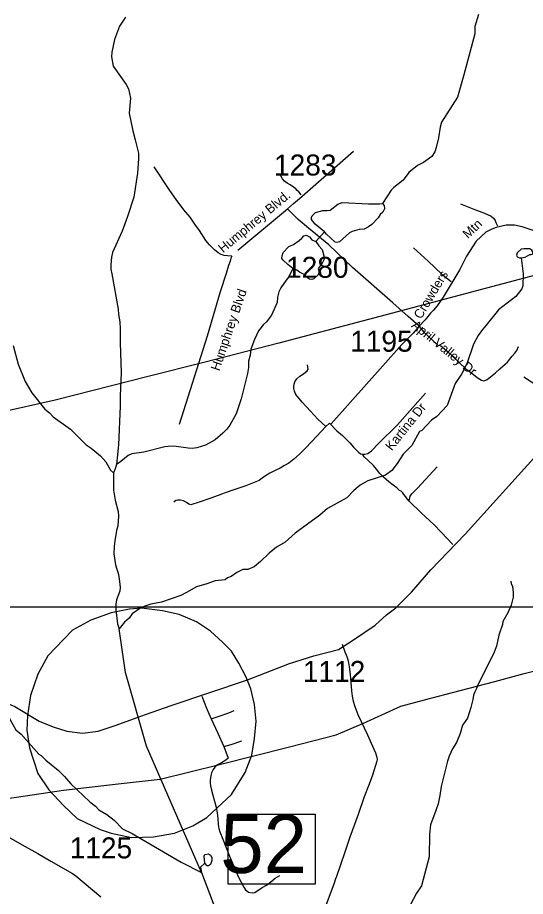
# Model space of a CAD drawing. Extents: x 1268485 to 1426702, y 514839 to 616766.
# Drawn here: x 1319574 to 1323145, y 527765 to 533949 of the extents above; entities that cross this region are included whole.
import ezdxf

# ---------------------------------------------------------------- set-up
doc = ezdxf.new("R2010")
doc.units = 0
for name, color, linetype in [('Old_Level_10', 7, 'Continuous'), ('Old_Level_11', 7, 'Continuous'), ('Old_Level_3', 7, 'Continuous'), ('Old_Level_31', 7, 'Continuous'), ('Old_Level_32', 7, 'Continuous'), ('Old_Level_35', 7, 'Continuous'), ('Old_Level_50', 7, 'Continuous'), ('Old_Level_56', 7, 'Continuous'), ('Old_Level_59', 7, 'Continuous'), ('Old_Level_62', 7, 'Continuous'), ('Old_Level_63', 7, 'Continuous'), ('Old_Level_8', 7, 'Continuous')]:
    doc.layers.add(name, color=color, linetype=linetype)

msp = doc.modelspace()

# ---------------------------------------------------------------- linework, layer by layer
at = {"layer": 'Old_Level_3'}
msp.add_lwpolyline([(1320374.254, 528179.02), (1320529.254, 528185.479), (1320677.796, 528211.312), (1320806.963, 528262.979), (1320903.838, 528321.103), (1321078.213, 528482.562), (1321175.088, 528637.562), (1321220.296, 528760.27), (1321239.671, 528876.521), (1321252.588, 528999.229), (1321239.671, 529115.479), (1321213.838, 529225.271), (1321181.546, 529309.229), (1321129.88, 529406.104), (1321078.213, 529490.062), (1321013.629, 529554.645), (1320929.671, 529632.146), (1320832.796, 529696.729), (1320710.088, 529748.396), (1320593.837, 529774.229), (1320445.296, 529793.604), (1320361.338, 529787.145), (1320232.171, 529761.312), (1320090.088, 529709.646), (1319960.921, 529638.604), (1319896.338, 529574.02), (1319786.546, 529457.77), (1319715.504, 529328.604), (1319663.838, 529180.062), (1319644.463, 529037.979), (1319638.004, 528934.646), (1319657.379, 528811.937), (1319715.504, 528631.104), (1319793.004, 528514.854), (1319896.338, 528405.062), (1319993.213, 528314.645), (1320154.671, 528237.145), (1320232.171, 528211.312), (1320374.254, 528179.02)], dxfattribs=at)
at = {"layer": 'Old_Level_31'}
msp.add_line((1320424.412, 529026.51), (1320424.412, 529026.51), dxfattribs=at)
msp.add_lwpolyline([(1321054.079, 528343.583), (1321665.834, 528343.583), (1321665.834, 527851.725), (1321054.079, 527851.725), (1321054.079, 528343.583)], dxfattribs=at)
at = {"layer": 'Old_Level_32'}
msp.add_line((1321122.398, 532313.014), (1321471.76, 532603.131), dxfattribs=at)
for points in [[(1321471.76, 532603.131), (1321513.515, 532640.421), (1321556.826, 532675.62), (1321936.012, 533008.804)], [(1322397.94, 531778.778), (1322321.212, 531846.106), (1322213.13, 531941.677), (1321928.472, 532191.922), (1321763.389, 532350.705), (1321620.563, 532466.815), (1321547.67, 532527.679), (1321507.453, 532567.416), (1321471.76, 532603.131)], [(1323957.426, 532145.829), (1323546.481, 532304.305), (1323430.573, 532355.426), (1323346.276, 532390.188), (1323270.41, 532428.019), (1323184.006, 532456.646), (1323122.891, 532477.095), (1323068.098, 532489.364), (1323009.09, 532489.364), (1322939.545, 532473.005), (1322907.935, 532460.737), (1322865.786, 532440.288), (1322798.349, 532376.898), (1322730.911, 532270.566), (1322682.686, 532177.311), (1322565.361, 531981.792), (1322523.219, 531920.864), (1322499.107, 531891.281), (1322477.75, 531868.86), (1322439.348, 531823.596), (1322397.94, 531778.778)], [(1322397.94, 531778.778), (1322356.401, 531729.282), (1322275.71, 531647.907), (1321778.36, 531091.708)], [(1320422.195, 529026.86), (1320473.092, 529045.164), (1320653.021, 529108.515), (1321189.477, 529288.566), (1321486.026, 529405.266), (1321655.96, 529458.614), (1321831.317, 529503.547), (1321936.928, 529571.055), (1322087.268, 529673.681), (1322167.162, 529745.909), (1322234.211, 529796.385), (1322342.868, 529905.853), (1322480.695, 530062.757), (1322720.696, 530315.252), (1323225.707, 530872.787), (1323239.898, 530886.275)], [(1318113.271, 529418.979), (1318158.493, 529431.424), (1318177.54, 529434.146), (1318193.865, 529439.591), (1318283.655, 529450.482), (1318340.795, 529458.65), (1318487.724, 529450.482), (1318850.398, 529355.252), (1319336.873, 529191.872), (1319553.454, 529101.847), (1319726.719, 528998.484), (1319823.348, 528958.473), (1319919.976, 528928.464), (1320029.933, 528915.127), (1320139.89, 528928.464), (1320259.843, 528968.475), (1320422.195, 529026.86)], [(1318113.271, 529418.979), (1318114.959, 529292.566), (1318123.121, 529082.92), (1318131.284, 528971.289), (1318150.33, 528884.163), (1318166.656, 528846.045), (1318215.633, 528756.196), (1318259.167, 528704.466), (1318338.073, 528647.289), (1318422.422, 528606.448), (1318650.476, 528511.012), (1318777.093, 528471.001), (1318970.351, 528387.644), (1319130.287, 528327.627), (1319193.596, 528304.286), (1319480.149, 528200.923), (1319606.767, 528127.57), (1319716.723, 528067.552), (1319806.687, 528014.204), (1319959.961, 527927.513), (1319983.285, 527910.841), (1320159.863, 527763.521)]]:
    msp.add_lwpolyline(points, dxfattribs=at)
at = {"layer": 'Old_Level_35'}
for p, q in [((1323489.705, 531183.886), (1323134.247, 531418.619)), ((1321768.293, 531096.072), (1321740.201, 531071.568))]:
    msp.add_line(p, q, dxfattribs=at)
for points in [[(1321080.035, 532269.739), (1321048.97, 532273.122), (1321026.517, 532276.454), (1321005.499, 532282.298), (1320984.584, 532293.986), (1320957.824, 532315.773), (1320924.503, 532349.197), (1320898.462, 532381.748), (1320853.35, 532451.21), (1320820.747, 532496.321), (1320788.144, 532544.816), (1320743.853, 532597.463), (1320687.873, 532668.514), (1320645.223, 532732.9), (1320533.982, 532900.12)], [(1321567.342, 532701.117), (1321551.45, 532722.852), (1321540.582, 532733.772), (1321529.715, 532743.768), (1321513.003, 532756.328), (1321490.345, 532771.399), (1321470.352, 532784.727), (1321450.257, 532798.927), (1321436.826, 532813.998), (1321416.834, 532847.422)], [(1322688.772, 532639.704), (1322781.045, 532600.949), (1322856.402, 532572.447), (1322904.281, 532551.941), (1322920.891, 532539.126), (1322932.784, 532522.261), (1322937.295, 532508.573), (1322947.547, 532483.506)], [(1322356.895, 532328.435), (1322460.651, 532234.931), (1322557.538, 532144.811), (1322623.77, 532092.369)], [(1321080.035, 532269.739), (1321074.089, 532257.179), (1321068.245, 532234.623), (1321057.377, 532205.353), (1321040.665, 532148.553), (1320998.015, 532019.831), (1320906.869, 531707.127), (1320710.327, 531086.024)], [(1322397.905, 531787.815), (1322403.749, 531766.9), (1322432.149, 531734.296), (1322498.586, 531672.883), (1322516.22, 531655.3), (1322529.651, 531645.253), (1322544.62, 531641.049), (1322558.871, 531633.565), (1322596.498, 531599.269), (1322679.954, 531523.195), (1322725.989, 531477.263), (1322767.922, 531447.121), (1322793.758, 531427.077), (1322813.033, 531412.877), (1322834.769, 531396.935), (1322847.277, 531393.602), (1322859.785, 531396.115), (1322874.856, 531403.65), (1322899.155, 531421.182), (1322933.399, 531448.813), (1322965.079, 531478.084), (1322984.354, 531493.924), (1323002.706, 531510.687), (1323017.778, 531525.707), (1323032.849, 531543.239), (1323052.124, 531567.486), (1323069.656, 531588.453), (1323083.907, 531607.626), (1323096.415, 531636.076)], [(1321740.201, 531071.568), (1321686.169, 531124.061), (1321632.753, 531179.99), (1321575.031, 531243.863), (1321531.253, 531297.228), (1321520.795, 531320.809), (1321517.207, 531338.29), (1321516.386, 531353.207), (1321518.129, 531368.945), (1321523.358, 531387.297), (1321536.481, 531408.315), (1321558.422, 531425.795), (1321576.774, 531437.176), (1321596.049, 531452.914), (1321610.915, 531463.422), (1321616.144, 531473.06), (1321614.401, 531489.618), (1321612.658, 531505.356)], [(1321998.361, 530877.384), (1322014.97, 530876.513), (1322035.988, 530882.612), (1322062.235, 530901.016), (1322113.703, 530955.253), (1322242.373, 531081.205), (1322353.511, 531205.364), (1322441.786, 531305.994)], [(1321768.293, 531096.072), (1321818.12, 531042.707), (1321858.413, 531007.694), (1321883.737, 530982.319), (1321909.984, 530956.124), (1321936.23, 530927.263), (1321958.171, 530903.63), (1321972.115, 530890.507), (1321985.238, 530880.87), (1321998.361, 530877.384)], [(1321740.201, 531071.568), (1321642.391, 530967.504), (1321596.049, 530916.754), (1321556.577, 530877.384), (1321517.207, 530843.242), (1321480.502, 530814.382), (1321451.59, 530796.952), (1321420.114, 530779.42), (1321384.333, 530761.939), (1321347.628, 530742.664), (1321317.896, 530724.312), (1321294.212, 530707.703), (1321271.452, 530692.837), (1321236.49, 530677.92), (1321178.768, 530654.339), (1321102.591, 530629.015), (1321026.619, 530601.896), (1321003.038, 530593.131), (1320932.09, 530566.884), (1320851.607, 530539.765), (1320791.22, 530521.362), (1320779.019, 530526.642), (1320761.487, 530536.229), (1320740.469, 530548.48), (1320719.451, 530552.889), (1320701.202, 530554.632), (1320686.335, 530551.146), (1320673.212, 530539.765)], [(1322326.855, 530547.814), (1322313.424, 530563.449), (1322303.786, 530576.367), (1322290.868, 530594.053), (1322282.768, 530604.921), (1322270.465, 530615.891), (1322260.213, 530621.325), (1322239.708, 530640.293), (1322215.204, 530658.696), (1322185.471, 530683.199), (1322147.024, 530715.547), (1322120.777, 530741.793), (1322098.017, 530771.577), (1322076.076, 530797.823), (1322038.654, 530833.605), (1322011.485, 530858.981), (1321998.361, 530877.384)], [(1322326.855, 530547.814), (1322330.956, 530570.267), (1322334.339, 530581.801), (1322346.027, 530597.488), (1322385.397, 530636.96), (1322524.832, 530787.315)], [(1322634.125, 530240.851), (1322552.72, 530329.434), (1322503.712, 530379.825), (1322411.951, 530464.101), (1322326.855, 530547.814)], [(1321855.132, 529539.881), (1321873.792, 529487.643), (1321888.761, 529454.015), (1321897.476, 529422.949), (1321906.088, 529380.606), (1321912.342, 529325.857), (1321916.135, 529271.057), (1321922.389, 529212.617), (1321927.413, 529175.246), (1321933.462, 529139.209), (1321944.74, 529101.838), (1321967.091, 529045.808), (1322034.348, 528901.502), (1322079.152, 528800.668), (1322091.66, 528775.805), (1322096.581, 528752.121), (1322101.502, 528731.001), (1322100.272, 528717.314)], [(1320870.575, 529175.246), (1320903.383, 529091.175), (1320934.859, 529015.306)], [(1320934.859, 529015.306), (1320992.171, 529034.017), (1321058.608, 529057.29), (1321096.03, 529072.515)], [(1320934.859, 529015.306), (1320980.38, 528918.368), (1321023.646, 528821.481)], [(1321023.646, 528821.481), (1321075.012, 528835.475), (1321150.881, 528861.209)], [(1321023.646, 528821.481), (1321055.122, 528738.64), (1321037.59, 528724.644), (1321007.242, 528704.754), (1320980.38, 528690.76), (1320960.593, 528673.791), (1320948.905, 528657.439), (1320938.345, 528635.293), (1320932.501, 528616.634), (1320929.63, 528599.665), (1320927.887, 528580.442), (1320928.502, 528562.858), (1320930.245, 528543.635), (1320936.602, 528512.108), (1320947.162, 528478.839), (1320958.235, 528435.06), (1320969.41, 528392.46), (1320976.894, 528352.167), (1320981.61, 528314.182), (1320985.096, 528270.454), (1320989.71, 528242.414), (1320996.784, 528219.191), (1321018.007, 528168.8), (1321064.964, 528049.767), (1321127.71, 527900.899), (1321163.902, 527830.566), (1321176.205, 527812.573), (1321196.71, 527795.143), (1321222.957, 527790.735), (1321242.232, 527793.247), (1321293.905, 527828.106), (1321323.125, 527845.484), (1321353.575, 527868.552), (1321385.973, 527894.081), (1321417.141, 527913.356)], [(1322100.272, 528717.314), (1322070.54, 528618.992), (1322045.523, 528555.476)], [(1322045.523, 528555.476), (1322011.997, 528465.869), (1321969.654, 528342.684), (1321909.881, 528182.179), (1321873.792, 528076.372), (1321815.352, 527905.871), (1321809.406, 527889.006)], [(1321809.406, 527889.006), (1321799.153, 527859.837), (1321741.841, 527700.563)]]:
    msp.add_lwpolyline(points, dxfattribs=at)
at = {"layer": 'Old_Level_50'}
msp.add_line((1320424.412, 529029.179), (1320424.412, 529029.179), dxfattribs=at)
at = {"layer": 'Old_Level_56'}
for points in [[(1323366.294, 532177.376), (1322870.978, 532044.675), (1322166.251, 531856.96), (1321411.081, 531658.454), (1320883.684, 531522.597), (1320491.102, 531423.847), (1319838.818, 531256.887), (1319440.632, 531168.053), (1318922.163, 531078.039), (1318268.965, 530955.12), (1317830.82, 530869.291), (1317691.971, 530840.471), (1317442.112, 530764.26), (1316936.195, 530611.963), (1316289.347, 530416.88), (1315543.694, 530194.172)], [(1316620.183, 528035.863), (1316843.479, 528084.795), (1317196.816, 528132.51), (1317632.76, 528208.376), (1318074.503, 528274.122), (1318532.086, 528331.545), (1319071.956, 528401.118), (1319302.845, 528429.688), (1319565.859, 528463.613), (1319896.997, 528511.975), (1320280.295, 528557.086), (1320577.308, 528590.127), (1320993.978, 528692.595), (1321485.17, 528819.176), (1321813.193, 528901.617), (1322001.33, 528983.272), (1322268.275, 529103.161), (1322435.285, 529149.224), (1322684.902, 529213.434), (1322930.722, 529277.92), (1323135.933, 529333.018), (1323248.784, 529362.562)]]:
    msp.add_lwpolyline(points, dxfattribs=at)
at = {"layer": 'Old_Level_59'}
for points in [[(1320331.8, 533953.114), (1320290.38, 533889.958), (1320256.034, 533794.609), (1320236.041, 533707.205), (1320233.273, 533672.808), (1320246.645, 533608.097), (1320336.657, 533479.43), (1320352.731, 533447.263), (1320368.803, 533382.929), (1320359.159, 533276.778), (1320383.269, 533153.616), (1320401.723, 533089.23), (1320423.561, 532996.084), (1320424.689, 532956.663), (1320418.23, 532854.188), (1320392.393, 532686.507), (1320347.179, 532549.533), (1320308.835, 532446.904), (1320241.27, 532296.447), (1320234.401, 532264.613), (1320229.274, 532210.53), (1320228.557, 532178.542), (1320237.682, 532146.348), (1320281.87, 531896.852), (1320283.101, 531859.07), (1320291.918, 531808.833), (1320294.686, 531756.237), (1320294.583, 531662.682), (1320301.555, 531449.992), (1320295.814, 531288.462), (1320296.121, 531214.592), (1320283.716, 530944.077), (1320268.542, 530804.847)], [(1320268.542, 530804.847), (1320259.827, 530773.012), (1320247.216, 530747.022)], [(1320247.216, 530747.022), (1320248.344, 530624.709), (1320260.75, 530554.734), (1320280.845, 530473.893), (1320284.126, 530440.162), (1320278.487, 530372.187), (1320269.772, 530340.352), (1320258.084, 530268.379), (1320253.163, 530226.651), (1320251.83, 530174.927), (1320262.083, 530098.442), (1320282.485, 530029.903), (1320291.405, 529981.306), (1320294.378, 529939.425), (1320291.815, 529913.998), (1320270.387, 529852.072), (1320265.671, 529821.827), (1320264.748, 529782.457), (1320276.436, 529683.725), (1320287.612, 529647.379)], [(1320868.012, 527932.938), (1320480.361, 528822.916), (1320333.338, 529341.236), (1320287.612, 529647.379)], [(1320868.012, 527932.938), (1321005.823, 527570.152), (1321040.169, 527498.896), (1321119.627, 527388.937), (1321139.209, 527366.433), (1321165.969, 527315.836), (1321202.673, 527259.293), (1321225.229, 527198.905), (1321248.297, 527155.792), (1321269.212, 527107.759), (1321315.144, 527018.203), (1321344.364, 526983.959), (1321403.111, 526930.287), (1321462.269, 526888.866), (1321509.533, 526861.645), (1321561.104, 526838.474), (1321628.156, 526796.9), (1321681.572, 526769.577), (1321701.462, 526765.066), (1321737.039, 526746.303), (1321762.568, 526723.645), (1321837.309, 526670.434), (1321866.837, 526645.213), (1322074.756, 526496.539)]]:
    msp.add_lwpolyline(points, dxfattribs=at)
at = {"layer": 'Old_Level_62'}
for p, q in [((1321731.383, 532441.265), (1321671.816, 532372.726)), ((1320860.937, 527971.642), (1320889.542, 527998.965)), ((1320860.937, 527971.642), (1320868.012, 527932.938))]:
    msp.add_line(p, q, dxfattribs=at)
for points in [[(1322815.596, 533971.261), (1322789.657, 533885.6), (1322788.427, 533833.927), (1322711.737, 533545.829), (1322666.011, 533388.349), (1322555.795, 533212.466), (1322545.03, 533179.042), (1322533.24, 533102.968), (1322517.656, 533036.019), (1322506.993, 533005.876), (1322486.18, 532972.606), (1322427.125, 532929.494), (1322386.627, 532908.989), (1322325.419, 532860.135), (1322284.101, 532805.181), (1322218.997, 532754.79), (1322200.543, 532734.643), (1322140.36, 532642.319)], [(1321731.383, 532441.265), (1321666.69, 532495.091), (1321639.418, 532527.643), (1321639.725, 532541.586), (1321645.979, 532555.427), (1321668.535, 532577.112), (1321720.926, 532591.671), (1321750.966, 532591.056), (1321771.061, 532594.746), (1321826.015, 532635.5), (1321856.363, 532648.829), (1322042.14, 532638.525), (1322122.213, 532638.576), (1322140.36, 532642.319)], [(1322140.36, 532642.319), (1322151.945, 532628.118), (1322153.381, 532604.281), (1322142.82, 532579.88), (1322124.468, 532564.655), (1322110.012, 532541.176), (1322064.798, 532493.656), (1322042.447, 532476.072), (1322009.947, 532459.463), (1321975.908, 532457.72), (1321927.618, 532444.699), (1321907.318, 532433.626), (1321837.805, 532371.035), (1321819.761, 532365.652), (1321807.868, 532370.009), (1321745.019, 532425.424), (1321731.383, 532441.265)], [(1321509.312, 532184.796), (1321473.941, 532211.76), (1321440.62, 532241.954), (1321432.828, 532254.463), (1321433.34, 532272.507), (1321441.85, 532296.088), (1321480.912, 532339.662), (1321513.208, 532352.938), (1321553.911, 532381.646), (1321572.366, 532397.691), (1321586.719, 532414.659), (1321602.816, 532418.453), (1321612.658, 532414.146), (1321626.602, 532405.637), (1321644.031, 532385.593), (1321671.816, 532372.726)], [(1321671.816, 532372.726), (1321693.141, 532342.737), (1321716.517, 532317.669), (1321730.973, 532253.386), (1321716.312, 532221.654), (1321687.4, 532184.488), (1321693.039, 532167.981), (1321692.731, 532154.038), (1321686.375, 532140.197), (1321657.667, 532111.234), (1321643.519, 532105.748), (1321627.525, 532107.748), (1321613.786, 532116.206), (1321588.36, 532140.504), (1321556.782, 532157.575), (1321536.994, 532171.929), (1321509.312, 532184.796)], [(1323115.895, 532259.127), (1323142.039, 532264.356), (1323176.488, 532281.734), (1323184.485, 532281.58), (1323196.686, 532287.066), (1323196.993, 532301.83), (1323189.201, 532313.466), (1323175.463, 532321.976), (1323135.478, 532322.745), (1323115.382, 532319.054), (1323086.778, 532294.191), (1323082.369, 532277.889), (1323084.112, 532270.457), (1323092.109, 532263.741), (1323101.952, 532259.435), (1323115.895, 532259.127)], [(1323115.895, 532259.127), (1323129.326, 532147.271), (1323127.378, 532061.149), (1323118.868, 532040.798), (1323077.55, 531985.844), (1322955.339, 531893.109), (1322860.503, 531772.744), (1322842.048, 531755.058), (1322813.033, 531712.151), (1322779.61, 531650.43), (1322732.345, 531511.917), (1322694.616, 531440.457), (1322651.042, 531374.02), (1322595.473, 531220.846), (1322521.654, 531142.773), (1322485.052, 531115.603), (1322415.232, 531044.758), (1322401.084, 531036.863), (1322346.745, 530938.643), (1322285.332, 530877.538), (1322243.809, 530812.69), (1322204.644, 530761.786), (1322161.89, 530730.669), (1322036.809, 530689.658), (1321982.162, 530658.747), (1321939.204, 530621.889), (1321888.043, 530571.241), (1321752.196, 530495.987), (1321699.088, 530446.979), (1321525.921, 530320.821), (1321454.563, 530259.101), (1321395.611, 530222.499), (1321342.605, 530181.744), (1321281.192, 530123.049), (1321236.388, 530085.37), (1321191.891, 530066.608), (1321157.853, 530065.634), (1321115.304, 530044.36), (1321076.652, 530017.19), (1321050.405, 530006.272), (1321034.104, 529994.276), (1320963.873, 529985.817), (1320905.331, 529965.671), (1320832.845, 529944.961), (1320761.795, 529902.925), (1320721.399, 529884.009), (1320586.27, 529836.693), (1320509.786, 529822.647), (1320469.39, 529807.884), (1320433.096, 529790.557), (1320380.09, 529753.852), (1320357.432, 529723.966), (1320326.777, 529695.002), (1320287.612, 529647.379)], [(1321509.312, 532184.796), (1321481.938, 532125.433), (1321461.33, 532102.057), (1321424.113, 532048.641), (1321411.4, 532018.55), (1321402.582, 531982.614), (1321399.609, 531944.936), (1321359.624, 531856.251), (1321324.458, 531808.577), (1321304.055, 531790.942), (1321266.94, 531744.088), (1321239.463, 531684.725), (1321213.935, 531615.469), (1321208.911, 531572.92), (1321197.94, 531531.295), (1321197.018, 531487.824), (1321189.943, 531445.275), (1321145.755, 531266.47), (1321111.306, 531161.278), (1321067.425, 531082.538), (1321044.664, 531052.652), (1321018.11, 531025.278), (1320963.053, 530978.782), (1320894.053, 530939.976), (1320865.859, 530930.697), (1320833.563, 530921.521), (1320801.472, 530918.036), (1320773.483, 530919.419), (1320671.674, 530933.773), (1320633.74, 530932.082), (1320609.646, 530928.493), (1320462.624, 530890.404), (1320376.297, 530879.844), (1320351.998, 530867.183), (1320300.94, 530826.377), (1320268.542, 530804.847)], [(1319543.58, 531641.715), (1319578.542, 531511.354), (1319627.857, 531389.706), (1319673.891, 531309.172), (1319765.242, 531194.907), (1319798.665, 531167.994), (1319824.091, 531139.594), (1319946.097, 531052.601), (1320055.595, 530943.718), (1320091.172, 530919.214), (1320155.866, 530865.388), (1320195.031, 530824.378), (1320227.531, 530763.836), (1320247.216, 530747.022)], [(1323042.999, 529983.408), (1323044.64, 529967.773), (1323054.174, 529947.062), (1323059.198, 529903.489), (1323058.378, 529871.501), (1323045.05, 529815.932), (1323021.776, 529759.799), (1322986.302, 529700.59), (1322983.842, 529679.316), (1322958.108, 529603.498), (1322942.319, 529527.526), (1322920.993, 529472.162), (1322812.008, 529258.497), (1322801.243, 529229.175), (1322788.735, 529204.825), (1322780.122, 529181.193), (1322775.509, 529151.768), (1322760.232, 529095.43), (1322736.446, 529020.432), (1322701.28, 528969.426), (1322685.798, 528911.447), (1322660.372, 528849.624), (1322631.357, 528804.256), (1322608.186, 528752.993), (1322597.318, 528717.109), (1322553.027, 528538.304), (1322543.697, 528476.121), (1322530.266, 528416.451), (1322515.195, 528369.187), (1322476.748, 528269.839), (1322471.211, 528204.325), (1322467.52, 528044.333), (1322414.72, 527839.434), (1322379.553, 527787.608), (1322314.654, 527669.139)], [(1319451.307, 529308.889), (1319462.175, 529258.6), (1319475.503, 529232.097), (1319487.806, 529159.611), (1319492.01, 529081.589), (1319520.409, 529012.897), (1319560.702, 528938.258), (1319599.97, 528907.09), (1319722.796, 528765.911), (1319740.635, 528758.17), (1319771.803, 528723.106), (1319858.335, 528653.235), (1319903.344, 528609.662), (1319948.148, 528558.706), (1320081.329, 528432.087), (1320120.597, 528400.97), (1320146.023, 528375.8), (1320201.285, 528342.684), (1320252.343, 528301.469), (1320310.885, 528240.363), (1320380.193, 528208.631), (1320723.655, 528006.399), (1320868.012, 527932.938)], [(1320889.542, 527998.965), (1320884.723, 528049.1), (1320890.977, 528060.481), (1320915.174, 528065.761), (1320930.963, 528055.559), (1320938.652, 528039.822), (1320940.087, 528017.625), (1320929.425, 527989.943), (1320917.224, 527980.357), (1320907.177, 527980.562), (1320889.542, 527998.965)]]:
    msp.add_lwpolyline(points, dxfattribs=at)
at = {"layer": 'Old_Level_63'}
for points in [[(1305516.95, 558564.883), (1305516.95, 529802.059), (1368033.021, 529802.059), (1368033.021, 573241.255), (1305516.95, 573241.255), (1305516.95, 558564.883)], [(1305516.95, 529802.059), (1368033.021, 529802.059), (1368033.021, 517504.204), (1305516.95, 517504.204), (1305516.95, 529802.059)]]:
    msp.add_lwpolyline(points, dxfattribs=at)

# ---------------------------------------------------------------- texts
at = {"layer": 'Old_Level_10'}
for s, height, rotation, p in [('Humphrey Blvd', 65.61666, 71.1112194, (1320991.925, 531458.276)), ('April Valley Dr', 65.61666, 320.8629972, (1322338.355, 531775.28)), ('Kartina Dr', 65.6167, 51.4276306, (1322205.135, 530896.56))]:
    msp.add_text(s, height=height, rotation=rotation, dxfattribs=at).set_placement(p)
at = {"layer": 'Old_Level_11'}
for s, height, rotation, p in [('Humphrey Blvd.', 65.61666, 39.7070167, (1321018.782, 532290.191)), ('Mtn', 65.6167, 43.2285833, (1322740.444, 532389.947)), ('Crowders', 65.6167, 59.0332028, (1322411.021, 531822.484))]:
    msp.add_text(s, height=height, rotation=rotation, dxfattribs=at).set_placement(p)
at = {"layer": 'Old_Level_31'}
msp.add_text('52', height=410.1042, dxfattribs=at).set_placement((1320999.065, 527930.253))
at = {"layer": 'Old_Level_8'}
for s, p in [('1283', (1321376.947, 532838.195)), ('1280', (1321461.734, 532118.407)), ('1195', (1321912.568, 531598.28)), ('1112', (1321579.483, 529274.815)), ('1125', (1319940.405, 528033.17))]:
    msp.add_text(s, height=147.6375, dxfattribs=at).set_placement(p)

doc.saveas('drawing.dxf')
